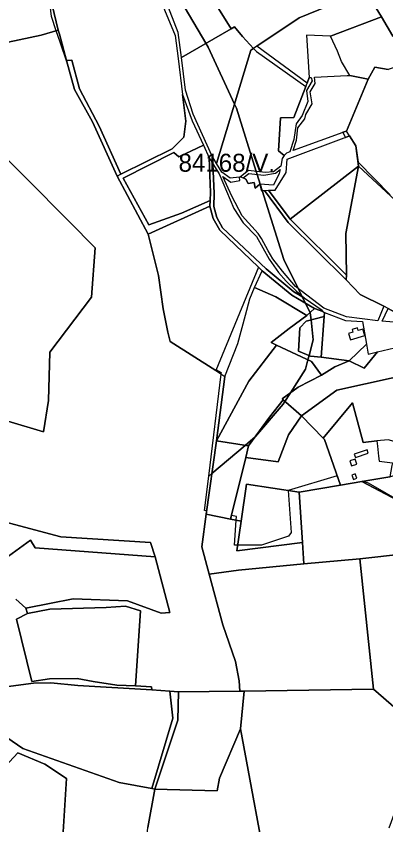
# Model space of a CAD drawing. Extents: x -477304 to -465429, y -1159113 to -1149210.
# Drawn here: x -476231 to -475923, y -1152741 to -1152067 of the extents above; entities that cross this region are included whole.
import ezdxf

# ---------------------------------------------------------------- set-up
doc = ezdxf.new("R2010")
doc.units = 0
for name, color, linetype in [('BPEJ_s', 7, 'Continuous'), ('orna_s', 7, 'Continuous'), ('PUPFL_s', 7, 'Continuous'), ('trav_porost_s', 7, 'Continuous'), ('zahrada_s', 7, 'Continuous')]:
    doc.layers.add(name, color=color, linetype=linetype)

msp = doc.modelspace()

# ---------------------------------------------------------------- linework, layer by layer
at = {"layer": 'BPEJ_s'}
for points in [[(-476104.5, -1152036), (-476072.83, -1152089.89), (-476071, -1152093), (-476049.05, -1152140.63), (-476047.5, -1152144), (-476031.02, -1152196.56), (-476030.22, -1152199.12), (-476027.7, -1152207.16), (-476026.04, -1152212.45), (-476008, -1152270), (-475996.04, -1152294.19), (-475993.04, -1152300.27), (-475992.64, -1152301.08), (-475990, -1152306.42), (-475987.68, -1152311.09), (-475986.12, -1152314.25), (-475986, -1152314.5), (-475985.36, -1152320.27), (-475983.5, -1152337), (-475986.98, -1152350.11), (-475987.91, -1152353.6), (-475990, -1152361.5), (-476002.58, -1152381.22), (-476007.06, -1152388.25), (-476008.5, -1152390.5), (-476031.5, -1152417.5), (-476032.06, -1152417.97), (-476035.81, -1152421.15), (-476040.24, -1152424.9), (-476067.81, -1152448.23), (-476070.5, -1152450.5), (-476060.12, -1152365.51), (-476060, -1152364.5), (-476064.41, -1152362.02), (-476064.65, -1152362.6), (-476102.53, -1152338.26), (-476104.66, -1152330.66), (-476108.38, -1152311.2), (-476112.29, -1152283.39), (-476120.87, -1152249), (-476146.74, -1152200.64), (-476167.13, -1152155.29), (-476182.36, -1152128.49), (-476188.37, -1152106.25), (-476194.23, -1152088.95), (-476197.48, -1152079.35), (-476201.5, -1152067.5), (-476203.83, -1152045.75)], [(-475907.61, -1152473.62), (-475937.5, -1152456.5), (-475942.48, -1152454.76), (-475943.04, -1152454.85), (-475960.94, -1152457.95), (-475963.59, -1152450.36), (-476004.4, -1152462.47), (-476004.5, -1152462.5), (-476002, -1152497.5), (-476004, -1152500.5), (-476026.5, -1152508), (-476046.41, -1152508), (-476049, -1152508), (-476047.7, -1152487.2), (-476047.5, -1152484), (-476051.64, -1152483.22), (-476052.4, -1152486.26), (-476072.51, -1152482.23), (-476072.11, -1152479.36), (-476074, -1152479), (-476070.5, -1152450.5), (-476067.81, -1152448.23), (-476040.24, -1152424.9), (-476035.81, -1152421.15), (-476032.06, -1152417.97), (-476031.5, -1152417.5), (-476008.5, -1152390.5), (-476007.06, -1152388.25), (-476002.58, -1152381.22), (-475990, -1152361.5), (-475987.91, -1152353.6), (-475986.98, -1152350.11), (-475983.5, -1152337), (-475985.36, -1152320.27), (-475986, -1152314.5), (-475986.12, -1152314.25), (-475987.68, -1152311.09), (-475990, -1152306.42), (-475992.64, -1152301.08), (-475993.04, -1152300.27), (-475996.04, -1152294.19), (-476008, -1152270), (-476026.04, -1152212.45), (-476027.7, -1152207.16), (-476030.22, -1152199.12), (-476031.02, -1152196.56), (-476047.5, -1152144), (-476049.05, -1152140.63), (-476071, -1152093), (-476072.83, -1152089.89), (-476104.5, -1152036)], [(-475907.61, -1152473.62), (-475937.5, -1152456.5), (-475942.48, -1152454.76), (-475943.04, -1152454.85), (-475960.94, -1152457.95), (-475963.59, -1152450.36), (-476004.4, -1152462.47), (-476004.5, -1152462.5), (-476002, -1152497.5), (-476004, -1152500.5), (-476026.5, -1152508), (-476046.41, -1152508), (-476049, -1152508), (-476047.7, -1152487.2), (-476047.5, -1152484), (-476051.64, -1152483.22), (-476052.4, -1152486.26), (-476072.51, -1152482.23), (-476072.11, -1152479.36), (-476074, -1152479), (-476070.5, -1152450.5), (-476060.12, -1152365.51), (-476060, -1152364.5), (-476064.41, -1152362.02), (-476064.65, -1152362.6), (-476102.53, -1152338.26), (-476104.66, -1152330.66), (-476108.38, -1152311.2), (-476112.29, -1152283.39), (-476120.87, -1152249), (-476146.74, -1152200.64), (-476167.13, -1152155.29), (-476182.36, -1152128.49), (-476188.37, -1152106.25), (-476194.23, -1152088.95), (-476197.48, -1152079.35), (-476201.5, -1152067.5), (-476203.83, -1152045.75)], [(-475919.5, -1152216), (-475946.19, -1152188.87), (-475948.12, -1152175.43), (-475953.37, -1152167.06), (-475956.73, -1152168.32), (-475958.94, -1152164.04), (-475955.95, -1152162.94), (-475937.71, -1152119.66), (-475932.2, -1152109.72), (-475921.26, -1152111.59)], [(-475921.26, -1152111.59), (-475932.2, -1152109.72), (-475937.71, -1152119.66), (-475955.95, -1152162.94), (-475958.94, -1152164.04), (-475956.73, -1152168.32), (-475953.37, -1152167.06), (-475948.12, -1152175.43), (-475946.19, -1152188.87), (-475919.5, -1152216)], [(-476360.5, -1152753.5), (-476354.5, -1152739), (-476361, -1152730), (-476369.5, -1152689.5), (-476353, -1152621.5), (-476349, -1152622), (-476349.44, -1152630.94), (-476350.5, -1152652.5), (-476346.27, -1152656.73), (-476345.56, -1152657.44), (-476345.03, -1152657.96), (-476346, -1152674.5), (-476343.81, -1152674.73), (-476318, -1152677.5), (-476319.5, -1152709), (-476297.5, -1152717), (-476282.5, -1152690.5), (-476261, -1152702), (-476251, -1152704), (-476229.5, -1152681), (-476207, -1152690.5), (-476189, -1152702.5), (-476194, -1152782.5)], [(-476194, -1152782.5), (-476189, -1152702.5), (-476207, -1152690.5), (-476229.5, -1152681), (-476251, -1152704), (-476261, -1152702), (-476282.5, -1152690.5), (-476297.5, -1152717), (-476319.5, -1152709)]]:
    msp.add_lwpolyline(points, dxfattribs=at)
at = {"layer": 'orna_s'}
msp.add_lwpolyline([(-475986.88, -1152118.39), (-475988.69, -1152123.1), (-476030.37, -1152092.18), (-475995.14, -1152068.69), (-475940.17, -1152045.93), (-475926.84, -1152067.68), (-475969.03, -1152083.96), (-475989.09, -1152083.05)], close=True, dxfattribs=at)
at = {"layer": 'PUPFL_s'}
for points in [[(-475879.64, -1152098.1), (-475885.71, -1152099.92), (-475903.33, -1152084.05), (-475917.35, -1152083.86), (-475926.84, -1152067.68), (-475940.17, -1152045.93), (-475955.66, -1152018.87), (-475976.92, -1151982.8), (-475983.63, -1151971.97), (-475980.41, -1151969.73), (-475985.28, -1151962.9), (-475999.58, -1151942.81), (-476009.55, -1151928.81), (-476004.99, -1151926.62), (-475993.74, -1151940.5), (-475972.9, -1151971.34), (-475959.35, -1151994.84), (-475937.1, -1152032.28), (-475934.78, -1152035.27), (-475908.18, -1152072.15), (-475883.68, -1152094.57)], [(-475956.36, -1152248.29), (-475955.98, -1152283.1), (-476002.71, -1152236.47), (-475945.72, -1152192.11)], [(-475955.98, -1152283.1), (-475956.36, -1152248.29), (-475945.72, -1152192.11), (-475888.14, -1152245.7), (-475901.66, -1152267.38), (-475892.88, -1152286.21), (-475868.66, -1152318.11), (-475891.74, -1152326.49), (-475898.12, -1152328.8), (-475903.14, -1152327.98), (-475903.96, -1152323.38), (-475904.12, -1152320.39), (-475921.14, -1152310.85), (-475924.64, -1152308.98), (-475944.34, -1152299.09), (-475956, -1152286.84)], [(-476002.71, -1152236.47), (-475955.98, -1152283.1), (-475956, -1152286.84), (-476004.31, -1152239.31), (-476024.2, -1152212.42), (-476020.74, -1152212.37)], [(-476012.72, -1152438.51), (-476039.64, -1152434.96), (-476037.39, -1152425.35), (-476019.97, -1152401.25), (-476008.55, -1152386.94), (-475993.31, -1152400.34), (-476004.22, -1152416.18)], [(-475974.22, -1152419.9), (-475960.94, -1152457.95), (-475995.21, -1152463.88), (-476039.1, -1152457.14), (-476043.54, -1152488.03), (-476052.4, -1152486.26), (-476039.64, -1152434.96), (-476012.72, -1152438.51), (-476004.22, -1152416.18), (-475993.31, -1152400.34), (-475975.17, -1152418.93)], [(-475869.59, -1152493.76), (-475943.04, -1152454.85), (-475919.86, -1152451.18), (-475872.18, -1152434.94), (-475855.76, -1152463.16), (-475876.5, -1152470.03)], [(-475995.21, -1152463.88), (-475992.49, -1152505.84), (-476047.11, -1152512.87), (-476043.54, -1152488.03), (-476039.1, -1152457.14)], [(-475869.59, -1152493.76), (-475876.5, -1152470.03), (-475855.76, -1152463.16), (-475838.14, -1152507.52), (-475944.69, -1152519.41), (-475991.34, -1152523.64), (-475992.49, -1152505.84), (-475995.21, -1152463.88), (-475960.94, -1152457.95), (-475943.04, -1152454.85)], [(-475992.49, -1152505.84), (-475991.34, -1152523.64), (-476045.78, -1152528.94), (-476070.12, -1152532.05), (-476076.26, -1152509.38), (-476072.51, -1152482.23), (-476052.4, -1152486.26), (-476043.54, -1152488.03), (-476047.11, -1152512.87)], [(-476058.64, -1152574.37), (-476070.12, -1152532.05), (-476045.78, -1152528.94), (-475991.34, -1152523.64), (-475944.69, -1152519.41), (-475933.3, -1152628.12), (-476041.06, -1152629.7), (-476044.69, -1152629.69), (-476045.15, -1152621.1), (-476048.32, -1152604.86)], [(-476131.58, -1152625.35), (-476147.09, -1152624.57), (-476166.56, -1152621.6), (-476180.09, -1152619.21), (-476202.99, -1152619.38), (-476217.87, -1152621.74), (-476230.41, -1152569.73), (-476221.42, -1152565.08), (-476202.71, -1152561.41), (-476155.77, -1152559.98), (-476139.85, -1152558.97), (-476127.38, -1152562.86)], [(-476225.14, -1152677.39), (-476238.45, -1152668.27), (-476310.99, -1152672.67), (-476341.26, -1152674.46), (-476338.36, -1152659.97), (-476346.33, -1152657.57), (-476277.75, -1152645.57), (-476290.51, -1152622.88), (-476297.86, -1152614.72), (-476295.6, -1152611.77), (-476288.79, -1152618.16), (-476254.22, -1152628.1), (-476216.24, -1152623.05), (-476201.84, -1152622.66), (-476179.33, -1152624.9), (-476117.87, -1152628.54), (-476103.01, -1152629.57), (-476100.34, -1152652.08), (-476117.93, -1152710.76), (-476145.04, -1152705.66)], [(-476100.34, -1152652.08), (-476103.01, -1152629.57), (-476095.55, -1152630.13), (-476096.18, -1152653.87), (-476115.27, -1152711.25), (-476117.93, -1152710.76)], [(-476095.55, -1152630.13), (-476044.69, -1152629.69), (-476041.06, -1152629.7), (-476043.99, -1152661.17), (-476061.41, -1152702.22), (-476063.37, -1152712.72), (-476115.27, -1152711.25), (-476096.18, -1152653.87)], [(-476009.88, -1152912.46), (-476058.74, -1152928.66), (-476094.77, -1152885.67), (-476111.47, -1152857.44), (-476120.17, -1152809.72), (-476124.01, -1152771.31), (-476121.1, -1152743.18), (-476115.27, -1152711.25), (-476063.37, -1152712.72), (-476061.41, -1152702.22), (-476043.99, -1152661.17), (-476019.4, -1152794.43), (-476008.61, -1152867.38), (-476005.79, -1152878.69), (-476016.4, -1152882.41), (-476013.13, -1152895.03), (-476001, -1152898.8), (-475967.84, -1152915.62), (-475934.1, -1152930.88), (-475884.28, -1152950.17), (-475934.74, -1152978.95), (-475998.35, -1152967.09), (-476004.69, -1152938.85)]]:
    msp.add_lwpolyline(points, close=True, dxfattribs=at)
for points in [[(-476385.93, -1152041.34), (-476228.37, -1152013.99), (-476207.76, -1152029.86), (-476206.44, -1152035.19), (-476200.77, -1152058.14), (-476195.69, -1152078.81), (-476209.86, -1152083.11), (-476261.39, -1152093.82)], [(-476261.39, -1152093.82), (-476209.86, -1152083.11), (-476195.69, -1152078.81), (-476194.84, -1152082.29), (-476188.91, -1152104.23), (-476182.36, -1152128.49), (-476167.13, -1152155.29), (-476146.74, -1152200.64), (-476120.87, -1152249), (-476112.29, -1152283.39), (-476108.38, -1152311.2), (-476104.66, -1152330.66), (-476102.53, -1152338.26), (-476064.65, -1152362.6), (-476057.05, -1152367.48), (-476064.07, -1152421.13), (-476072.51, -1152482.23), (-476076.26, -1152509.38), (-476070.12, -1152532.05), (-476058.64, -1152574.37), (-476048.32, -1152604.86), (-476045.15, -1152621.1), (-476044.69, -1152629.69), (-476095.55, -1152630.13), (-476103.01, -1152629.57), (-476117.87, -1152628.54), (-476118.02, -1152625.96), (-476131.58, -1152625.35), (-476127.38, -1152562.86), (-476139.85, -1152558.97), (-476155.77, -1152559.98), (-476202.71, -1152561.41), (-476221.42, -1152565.08), (-476222.64, -1152560.45), (-476183.26, -1152552.75), (-476138.02, -1152554.37), (-476109.99, -1152564.57), (-476102.82, -1152564.12), (-476115.16, -1152517.85), (-476118.85, -1152505.74), (-476193.65, -1152501.15), (-476287.51, -1152475.98)], [(-475888.14, -1152245.7), (-475945.72, -1152192.11), (-475948.12, -1152175.43), (-475953.37, -1152167.06), (-475955.95, -1152162.94), (-475937.71, -1152119.66), (-475932.2, -1152109.72), (-475921.26, -1152111.59)], [(-476258.69, -1152165.85), (-476186.64, -1152238.36), (-476164.99, -1152260.27), (-476168.2, -1152301.42), (-476202.78, -1152347.21), (-476203.84, -1152387.48), (-476208.09, -1152413.57), (-476237.68, -1152404.74)], [(-476237.68, -1152404.74), (-476208.09, -1152413.57), (-476203.84, -1152387.48), (-476202.78, -1152347.21), (-476168.2, -1152301.42), (-476164.99, -1152260.27), (-476186.64, -1152238.36), (-476258.69, -1152165.85)], [(-476287.51, -1152475.98), (-476193.65, -1152501.15), (-476118.85, -1152505.74), (-476115.16, -1152517.85), (-476215.06, -1152510.36), (-476218.87, -1152503.78), (-476243.3, -1152521.63)], [(-476243.3, -1152521.63), (-476218.87, -1152503.78), (-476215.06, -1152510.36), (-476115.16, -1152517.85), (-476102.82, -1152564.12), (-476109.99, -1152564.57), (-476138.02, -1152554.37), (-476183.26, -1152552.75), (-476222.64, -1152560.45), (-476231.18, -1152552.91)], [(-475891.57, -1152664.28), (-475933.3, -1152628.12), (-475944.69, -1152519.41), (-475838.14, -1152507.52)], [(-476231.18, -1152552.91), (-476222.64, -1152560.45), (-476221.42, -1152565.08), (-476230.41, -1152569.73), (-476217.87, -1152621.74), (-476202.99, -1152619.38), (-476180.09, -1152619.21), (-476166.56, -1152621.6), (-476147.09, -1152624.57), (-476131.58, -1152625.35), (-476118.02, -1152625.96), (-476117.87, -1152628.54), (-476179.33, -1152624.9), (-476201.84, -1152622.66), (-476216.24, -1152623.05), (-476254.22, -1152628.1)], [(-476019.4, -1152794.43), (-476043.99, -1152661.17), (-476041.06, -1152629.7), (-475933.3, -1152628.12), (-475891.57, -1152664.28), (-475920.52, -1152743.76)], [(-476238.45, -1152668.27), (-476225.14, -1152677.39), (-476145.04, -1152705.66), (-476117.93, -1152710.76), (-476115.27, -1152711.25), (-476121.1, -1152743.18)]]:
    msp.add_lwpolyline(points, dxfattribs=at)
at = {"layer": 'trav_porost_s'}
for points in [[(-476087.76, -1152020.01), (-476095.93, -1152002.34), (-476110.55, -1151970.26), (-476107.39, -1151969.19), (-476100.15, -1151984.73), (-476092.83, -1152001.11), (-476050.28, -1151981.13), (-476056.71, -1151966.62), (-476052.03, -1151964.67), (-476041.55, -1151985.75), (-476035.35, -1151997.35), (-475976.92, -1151982.8), (-475955.66, -1152018.87), (-475940.17, -1152045.93), (-475995.14, -1152068.69), (-476030.37, -1152092.18), (-476033.23, -1152094.09), (-476042.53, -1152084.12), (-476048.96, -1152076.19), (-476051.86, -1152077.85)], [(-476114.42, -1152032.62), (-476125.59, -1152017.3), (-476095.93, -1152002.34), (-476087.76, -1152020.01), (-476051.86, -1152077.85), (-476093.18, -1152101.58), (-476095.91, -1152080.75)], [(-476142.31, -1152034.43), (-476118.43, -1152035.16), (-476098.51, -1152083.5), (-476096.08, -1152102.39), (-476092.31, -1152132.65), (-476089.45, -1152154.81), (-476091.32, -1152167.94), (-476100.83, -1152177.75), (-476143.54, -1152199.03), (-476161.78, -1152158.99), (-476177.95, -1152127.71), (-476184.38, -1152103.85), (-476188.91, -1152104.23), (-476194.84, -1152082.29), (-476195.69, -1152078.81), (-476200.77, -1152058.14), (-476206.44, -1152035.19), (-476174.44, -1152026.6)], [(-475960.07, -1152105.09), (-475963.39, -1152096.55), (-475969.03, -1152083.96), (-475926.84, -1152067.68), (-475917.35, -1152083.86), (-475903.33, -1152084.05), (-475885.71, -1152099.92), (-475921.26, -1152111.59), (-475932.2, -1152109.72), (-475937.71, -1152119.66), (-475953.07, -1152116.76)], [(-476035.34, -1152095.48), (-476064.05, -1152189.99), (-476067.94, -1152183.33), (-476083.38, -1152148.96), (-476089.77, -1152128.95), (-476093.18, -1152101.58), (-476051.86, -1152077.85), (-476048.96, -1152076.19), (-476042.53, -1152084.12), (-476033.23, -1152094.09)], [(-476059.67, -1152197.29), (-476064.05, -1152189.99), (-476035.34, -1152095.48), (-476033.23, -1152094.09), (-476030.68, -1152096.82), (-475989.78, -1152125.94), (-475999.69, -1152151.73), (-476010.91, -1152151.85), (-476012.45, -1152179.35), (-476007.68, -1152183.3), (-476009.25, -1152185.82), (-476010.55, -1152192.18), (-476016.62, -1152196.86), (-476023.46, -1152197.49), (-476037.47, -1152195.76), (-476043.98, -1152201.23), (-476044.98, -1152201.33), (-476052.62, -1152202.1)], [(-476188.91, -1152104.23), (-476184.38, -1152103.85), (-476177.95, -1152127.71), (-476161.78, -1152158.99), (-476143.54, -1152199.03), (-476146.74, -1152200.64), (-476167.13, -1152155.29), (-476182.36, -1152128.49)], [(-475989.22, -1152129.06), (-475987.97, -1152138.34), (-475992.8, -1152150), (-475997.72, -1152157.03), (-475999.66, -1152169.94), (-476002.99, -1152180.24), (-476005.87, -1152181.3), (-476007.68, -1152183.3), (-476012.45, -1152179.35), (-476010.91, -1152151.85), (-475999.69, -1152151.73), (-475989.78, -1152125.94), (-475988.69, -1152123.1), (-475986.88, -1152118.39), (-475985.3, -1152118.3), (-475984.36, -1152121.22)], [(-475981.9, -1152123.22), (-475982.48, -1152118.14), (-475955.42, -1152116.56), (-475953.07, -1152116.76), (-475937.71, -1152119.66), (-475955.95, -1152162.94), (-476000.1, -1152179.18), (-475997.57, -1152170.45), (-475996.34, -1152160.22), (-475990.4, -1152152.85), (-475989.65, -1152149.06), (-475984.44, -1152140.22), (-475985.98, -1152130.18)], [(-476100.83, -1152177.75), (-476091.32, -1152167.94), (-476089.45, -1152154.81), (-476092.31, -1152132.65), (-476084.29, -1152154.37), (-476074.74, -1152174.69), (-476095.51, -1152184.47), (-476099.58, -1152180.85), (-476141.77, -1152202.2), (-476120.25, -1152241.14), (-476093.29, -1152231.33), (-476069.38, -1152220.75), (-476069.56, -1152225.58), (-476120.87, -1152249), (-476146.74, -1152200.64), (-476143.54, -1152199.03)], [(-475945.72, -1152192.11), (-476002.71, -1152236.47), (-476020.74, -1152212.37), (-476015.17, -1152212.18), (-476006.17, -1152197.49), (-476005.25, -1152186.44), (-475953.37, -1152167.06), (-475948.12, -1152175.43)], [(-476141.77, -1152202.2), (-476099.58, -1152180.85), (-476095.51, -1152184.47), (-476074.74, -1152174.69), (-476070.2, -1152185.3), (-476068.97, -1152214.13), (-476069.38, -1152220.75), (-476093.29, -1152231.33), (-476120.25, -1152241.14)], [(-475976.13, -1152312.12), (-475975.45, -1152313.42), (-475982.51, -1152310.78), (-476001.39, -1152299.78), (-476026.11, -1152279.54), (-476029.22, -1152276.52), (-476061.31, -1152245.45), (-476066.9, -1152235.81), (-476069.56, -1152225.58), (-476069.38, -1152220.75), (-476068.97, -1152214.13), (-476070.2, -1152185.3), (-476067, -1152190.42), (-476065.87, -1152214.91), (-476066.33, -1152225.95), (-476063.85, -1152234.95), (-476058.96, -1152243.57), (-476022.61, -1152277.77), (-475999.78, -1152296.96), (-475991.02, -1152302.01)], [(-476066.33, -1152225.95), (-476065.87, -1152214.91), (-476067, -1152190.42), (-476061.83, -1152198.69), (-476049.5, -1152227.64), (-476041.82, -1152239.36), (-476030.8, -1152250.88), (-476020.3, -1152269.77), (-476012.5, -1152280.82), (-476006.03, -1152288.11), (-475997.83, -1152296.13), (-475991.02, -1152302.01), (-475999.78, -1152296.96), (-476022.61, -1152277.77), (-476058.96, -1152243.57), (-476063.85, -1152234.95)], [(-476039.59, -1152202.96), (-476041.89, -1152201.86), (-476037.09, -1152198.4), (-476024.71, -1152199.7), (-476015.06, -1152198.02), (-476011.1, -1152194.9), (-476011.8, -1152198.35), (-476016.72, -1152208.15), (-476027.9, -1152207.14), (-476031.91, -1152210.69), (-476032.67, -1152205.94), (-476037.67, -1152206.71)], [(-476058.85, -1152200.81), (-476052.04, -1152205.65), (-476044.6, -1152204.21), (-476044.98, -1152201.33), (-476043.98, -1152201.23), (-476041.89, -1152201.86), (-476039.59, -1152202.96), (-476037.67, -1152206.71), (-476032.67, -1152205.94), (-476031.91, -1152210.69), (-476027.9, -1152207.14), (-476026.94, -1152212.47), (-476024.2, -1152212.42), (-476004.31, -1152239.31), (-475956, -1152286.84), (-475944.34, -1152299.09), (-475924.64, -1152308.98), (-475929.68, -1152320.98), (-475955.88, -1152317.72), (-475974.6, -1152310.66), (-475998.29, -1152292.46), (-476009.06, -1152279.69), (-476017.03, -1152269.51), (-476021.16, -1152262.69), (-476026.46, -1152252.42), (-476029.43, -1152248.38), (-476042.8, -1152233.59), (-476051.22, -1152217.36)], [(-476029.22, -1152276.52), (-476064.65, -1152362.6), (-476102.53, -1152338.26), (-476104.66, -1152330.66), (-476108.38, -1152311.2), (-476112.29, -1152283.39), (-476120.87, -1152249), (-476069.56, -1152225.58), (-476066.9, -1152235.81), (-476061.31, -1152245.45)], [(-476001.39, -1152299.78), (-475982.51, -1152310.78), (-475988.77, -1152316.79), (-476014.64, -1152301.04), (-476032.4, -1152293.41), (-476026.11, -1152279.54)], [(-476039.93, -1152316.39), (-476036.21, -1152302.91), (-476032.4, -1152293.41), (-476014.64, -1152301.04), (-475988.77, -1152316.79), (-476003.5, -1152327.55), (-476018.62, -1152339.12), (-476014.04, -1152341.28), (-476037, -1152371.48), (-476064.07, -1152421.13), (-476057.05, -1152367.48), (-476046.3, -1152339.86)], [(-475976.95, -1152351.37), (-475953.51, -1152354.4), (-475965.47, -1152359.38), (-475976.75, -1152366.49), (-475985.03, -1152354.96), (-476014.04, -1152341.28), (-476018.62, -1152339.12), (-476003.5, -1152327.55), (-475988.77, -1152316.79), (-475982.51, -1152310.78), (-475975.45, -1152313.42), (-475974.15, -1152314.16), (-475974.4, -1152317.5), (-475989.3, -1152321.26), (-475994.67, -1152326.92), (-475995.87, -1152346.27), (-475985.75, -1152350.64)], [(-475926.18, -1152321.51), (-475921.14, -1152310.85), (-475904.12, -1152320.39), (-475903.96, -1152323.38)], [(-475994.67, -1152326.92), (-475989.3, -1152321.26), (-475974.4, -1152317.5), (-475976.95, -1152351.37), (-475985.75, -1152350.64), (-475995.87, -1152346.27)], [(-476009.43, -1152386.17), (-476008.55, -1152386.94), (-476019.97, -1152401.25), (-476037.39, -1152425.35), (-476064.07, -1152421.13), (-476037, -1152371.48), (-476014.04, -1152341.28), (-475985.03, -1152354.96), (-475976.75, -1152366.49), (-475995.95, -1152376.43)], [(-476008.55, -1152386.94), (-476009.43, -1152386.17), (-475995.95, -1152376.43), (-475976.75, -1152366.49), (-475965.47, -1152359.38), (-475953.51, -1152354.4), (-475941.26, -1152360.6), (-475930, -1152346.96), (-475896.97, -1152339.22), (-475889.3, -1152362.36), (-475894.81, -1152363.59), (-475963.93, -1152378.97), (-475993.31, -1152400.34)], [(-475939.23, -1152340.54), (-475937.77, -1152348.78), (-475930, -1152346.96), (-475941.26, -1152360.6), (-475953.51, -1152354.4)], [(-475963.93, -1152378.97), (-475894.81, -1152363.59), (-475895.88, -1152369.18), (-475890.17, -1152414.31), (-475885.16, -1152424.03), (-475900.11, -1152425.13), (-475903.15, -1152425.35), (-475921.12, -1152420.16), (-475930.52, -1152421.15), (-475941.97, -1152422.36), (-475950.85, -1152389.32), (-475975.17, -1152418.93), (-475993.31, -1152400.34)], [(-475919.86, -1152451.18), (-475943.04, -1152454.85), (-475960.94, -1152457.95), (-475974.22, -1152419.9), (-475975.17, -1152418.93), (-475950.85, -1152389.32), (-475941.97, -1152422.36), (-475930.52, -1152421.15), (-475930.05, -1152425.65), (-475929.18, -1152433.98), (-475928.75, -1152438.1), (-475917.53, -1152439.5), (-475918.11, -1152441.54)], [(-476052.4, -1152486.26), (-476072.51, -1152482.23), (-476064.07, -1152421.13), (-476037.39, -1152425.35), (-476039.64, -1152434.96)], [(-475938.76, -1152428.52), (-475949.33, -1152432.3), (-475948.35, -1152435.05), (-475937.78, -1152431.24)], [(-475953.02, -1152437.67), (-475951.66, -1152441.96), (-475947.37, -1152440.6), (-475948.73, -1152436.31)], [(-475947.13, -1152452.29), (-475948.55, -1152448.55), (-475951.35, -1152449.62), (-475949.93, -1152453.36)]]:
    msp.add_lwpolyline(points, close=True, dxfattribs=at)
at = {"layer": 'zahrada_s'}
for points in [[(-475974.4, -1152317.5), (-475974.15, -1152314.16), (-475956.68, -1152320.84), (-475942.59, -1152321.54), (-475939.23, -1152340.54), (-475953.51, -1152354.4), (-475976.95, -1152351.37)], [(-475942.29, -1152328.02), (-475946.11, -1152329.18), (-475946.81, -1152326.89), (-475951.2, -1152328.22), (-475950.5, -1152330.51), (-475954.18, -1152331.62), (-475952.57, -1152336.95), (-475940.68, -1152333.35)]]:
    msp.add_lwpolyline(points, close=True, dxfattribs=at)

# ---------------------------------------------------------------- texts
at = {"layer": 'BPEJ_s'}
msp.add_text('84168/V.', height=15, dxfattribs=at).set_placement((-476095.63, -1152196.89))

doc.saveas('drawing.dxf')
